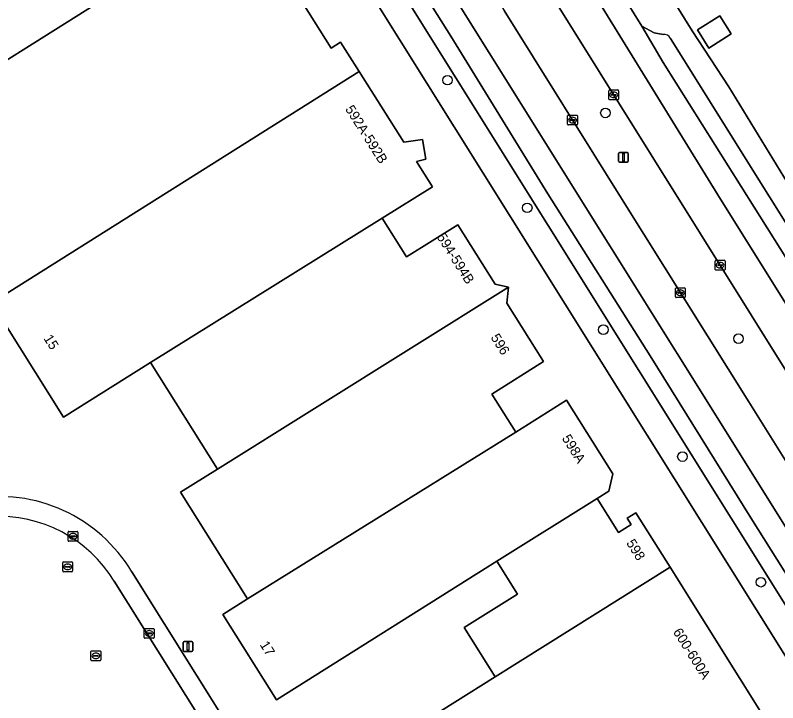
# Model space of a CAD drawing. Extents: x 158455 to 159797, y 387218 to 388672.
# Drawn here: x 158762.6 to 158840, y 387898.2 to 387968.1 of the extents above; entities that cross this region are included whole.
import ezdxf

# ---------------------------------------------------------------- set-up
doc = ezdxf.new("R2010")
doc.units = 0
for name, color, linetype in [('IMGEO_Berm_groen', 7, 'Continuous'), ('IMGEO_Boom', 7, 'Continuous'), ('IMGEO_Erf', 7, 'Continuous'), ('IMGEO_Kolk', 7, 'Continuous'), ('IMGEO_Lichtmast', 7, 'Continuous'), ('IMGEO_Pand', 7, 'Continuous'), ('IMGEO_Pand_nummerreeks', 7, 'Continuous'), ('IMGEO_Parkeervlak_open', 7, 'Continuous'), ('IMGEO_Rijbaan_lokaal_gesloten', 7, 'Continuous'), ('IMGEO_Rioolput', 7, 'Continuous'), ('IMGEO_Voetpad_open', 7, 'Continuous')]:
    doc.layers.add(name, color=color, linetype=linetype)

msp = doc.modelspace()

# ---------------------------------------------------------------- linework, layer by layer
at = {"layer": 'IMGEO_Berm_groen'}
msp.add_lwpolyline([(158816.975, 387970.262), (158811.283, 387979.426), (158807.11, 387976.831), (158812.237, 387968.597), (158824.322, 387949.219), (158837.096, 387928.793), (158852.17, 387904.676), (158856.298, 387907.238), (158851.263, 387915.352), (158842.383, 387929.569)], close=True, dxfattribs=at)
at = {"layer": 'IMGEO_Boom'}
for centre in [(158806.484, 387961.502), (158822.537, 387958.172), (158814.584, 387948.523), (158822.315, 387936.137), (158836.057, 387935.229), (158830.363, 387923.243), (158838.331, 387910.476)]:
    msp.add_circle(centre, 0.489, dxfattribs=at)
at = {"layer": 'IMGEO_Erf'}
for points in [[(158854.735, 387880.753), (158793.275, 387978.973), (158792.305, 387978.478), (158790.47, 387981.392), (158753.29, 388041.304)], [(158749.281, 387955.743), (158770.844, 387969.279), (158753.021, 387997.953)], [(158787.923, 387975.486), (158794.654, 387964.764), (158795.624, 387965.373), (158797.52, 387962.365), (158802.043, 387955.188), (158803.951, 387955.471), (158804.28, 387953.485), (158803.348, 387953.221), (158804.953, 387950.663), (158799.855, 387947.465), (158802.32, 387943.534), (158807.539, 387946.808), (158811.325, 387940.773), (158812.686, 387940.462), (158812.506, 387938.845), (158816.236, 387932.898), (158810.985, 387929.604), (158813.419, 387925.724), (158818.595, 387928.97), (158823.283, 387921.495), (158822.88, 387919.738), (158821.691, 387918.992), (158823.867, 387915.525), (158825.147, 387916.328), (158824.743, 387916.971), (158825.634, 387917.53), (158829.104, 387912), (158839.832, 387894.906)], [(158826.221, 387974.793), (158831.334, 387966.514), (158835.07, 387960.815), (158842.141, 387949.248), (158843.316, 387949.991), (158853.96, 387956.721), (158850.974, 387961.5), (158846.775, 387958.876), (158845.515, 387960.893), (158849.689, 387963.501), (158846.777, 387968.156)], [(158811.337, 387900.849), (158808.188, 387905.866), (158813.602, 387909.264), (158811.507, 387912.599), (158789.112, 387898.534), (158783.665, 387907.21), (158786.163, 387908.778), (158779.36, 387919.615), (158783.112, 387921.971), (158776.307, 387932.809), (158767.448, 387927.248), (158760.153, 387938.869)], [(158774.412, 387911.516), (158810.725, 387853.499), (158813.329, 387855.1), (158814.288, 387855.778), (158828.822, 387864.767), (158823.515, 387873.222), (158823.877, 387873.45), (158821.045, 387877.964), (158816.451, 387875.081), (158814.132, 387878.775), (158805.657, 387873.457), (158794.929, 387890.552), (158811.337, 387900.849)]]:
    msp.add_lwpolyline(points, dxfattribs=at)
msp.add_lwpolyline([(158831.874, 387966.612), (158834.159, 387968.04), (158835.311, 387966.196), (158833.027, 387964.768)], close=True, dxfattribs=at)
msp.add_arc((158760.897, 387903.456), 15.736, 30.80953, 100.02614, dxfattribs=at)
at = {"layer": 'IMGEO_Kolk'}
for p, q in [((158822.878, 387959.578), (158822.878, 387960.43)), ((158822.953, 387960.504), (158823.805, 387960.504)), ((158823.879, 387960.43), (158823.879, 387959.578)), ((158823.137, 387959.998), (158823.137, 387960.01)), ((158823.575, 387959.961), (158823.177, 387959.961)), ((158823.18, 387960.047), (158823.578, 387960.047)), ((158823.389, 387959.724), (158823.364, 387959.724)), ((158823.366, 387960.284), (158823.391, 387960.284)), ((158823.621, 387960.01), (158823.621, 387959.998)), ((158823.805, 387959.504), (158822.953, 387959.504)), ((158818.691, 387957.02), (158818.691, 387957.872)), ((158818.766, 387957.946), (158819.618, 387957.946)), ((158818.95, 387957.44), (158818.95, 387957.452)), ((158819.388, 387957.403), (158818.99, 387957.403)), ((158818.993, 387957.489), (158819.391, 387957.489)), ((158819.179, 387957.726), (158819.204, 387957.726)), ((158819.434, 387957.452), (158819.434, 387957.44)), ((158819.692, 387957.872), (158819.692, 387957.02)), ((158819.618, 387956.946), (158818.766, 387956.946)), ((158819.202, 387957.166), (158819.177, 387957.166)), ((158833.686, 387942.268), (158833.686, 387943.12)), ((158833.761, 387943.194), (158834.613, 387943.194)), ((158833.945, 387942.688), (158833.945, 387942.7)), ((158834.383, 387942.651), (158833.985, 387942.651)), ((158833.988, 387942.737), (158834.386, 387942.737)), ((158834.174, 387942.974), (158834.199, 387942.974)), ((158834.429, 387942.7), (158834.429, 387942.688)), ((158834.687, 387943.12), (158834.687, 387942.268)), ((158834.613, 387942.194), (158833.761, 387942.194)), ((158834.197, 387942.414), (158834.172, 387942.414)), ((158829.652, 387939.471), (158829.652, 387940.323)), ((158829.727, 387940.397), (158830.579, 387940.397)), ((158830.653, 387940.323), (158830.653, 387939.471)), ((158829.911, 387939.891), (158829.911, 387939.903)), ((158830.349, 387939.854), (158829.951, 387939.854)), ((158829.954, 387939.94), (158830.352, 387939.94)), ((158830.163, 387939.617), (158830.138, 387939.617)), ((158830.14, 387940.177), (158830.165, 387940.177)), ((158830.395, 387939.903), (158830.395, 387939.891)), ((158830.579, 387939.397), (158829.727, 387939.397)), ((158767.922, 387914.715), (158767.922, 387915.567)), ((158767.997, 387915.641), (158768.849, 387915.641)), ((158768.923, 387915.567), (158768.923, 387914.715)), ((158768.181, 387915.135), (158768.181, 387915.147)), ((158768.619, 387915.098), (158768.221, 387915.098)), ((158768.224, 387915.184), (158768.622, 387915.184)), ((158768.433, 387914.861), (158768.408, 387914.861)), ((158768.41, 387915.421), (158768.435, 387915.421)), ((158768.665, 387915.147), (158768.665, 387915.135)), ((158768.849, 387914.641), (158767.997, 387914.641)), ((158775.67, 387904.847), (158775.67, 387905.699)), ((158775.745, 387905.773), (158776.597, 387905.773)), ((158776.158, 387905.553), (158776.183, 387905.553)), ((158776.671, 387905.699), (158776.671, 387904.847)), ((158776.597, 387904.773), (158775.745, 387904.773)), ((158775.929, 387905.267), (158775.929, 387905.279)), ((158776.367, 387905.23), (158775.969, 387905.23)), ((158775.972, 387905.316), (158776.37, 387905.316)), ((158776.181, 387904.993), (158776.156, 387904.993)), ((158776.413, 387905.279), (158776.413, 387905.267))]:
    msp.add_line(p, q, dxfattribs=at)
for points in [[(158822.878, 387959.578), (158822.878, 387960.43)], [(158822.953, 387960.504), (158823.805, 387960.504)], [(158823.879, 387960.43), (158823.879, 387959.578)], [(158823.805, 387959.504), (158822.953, 387959.504)], [(158818.691, 387957.02), (158818.691, 387957.872)], [(158818.766, 387957.946), (158819.618, 387957.946)], [(158819.692, 387957.872), (158819.692, 387957.02)], [(158819.618, 387956.946), (158818.766, 387956.946)], [(158833.686, 387942.268), (158833.686, 387943.12)], [(158833.761, 387943.194), (158834.613, 387943.194)], [(158834.687, 387943.12), (158834.687, 387942.268)], [(158834.613, 387942.194), (158833.761, 387942.194)], [(158829.652, 387939.471), (158829.652, 387940.323)], [(158829.727, 387940.397), (158830.579, 387940.397)], [(158830.653, 387940.323), (158830.653, 387939.471)], [(158830.579, 387939.397), (158829.727, 387939.397)], [(158767.922, 387914.715), (158767.922, 387915.567)], [(158767.997, 387915.641), (158768.849, 387915.641)], [(158768.923, 387915.567), (158768.923, 387914.715)], [(158768.849, 387914.641), (158767.997, 387914.641)], [(158775.67, 387904.847), (158775.67, 387905.699)], [(158775.745, 387905.773), (158776.597, 387905.773)], [(158776.671, 387905.699), (158776.671, 387904.847)], [(158776.597, 387904.773), (158775.745, 387904.773)]]:
    msp.add_lwpolyline(points, dxfattribs=at)
for centre, radius, start, end in [((158822.955, 387960.428), 0.0765, 91.55205, 178.44795), ((158822.955, 387960.428), 0.0765, 91.55205, 178.44795), ((158823.803, 387960.428), 0.0765, 1.55205, 88.44795), ((158823.803, 387960.428), 0.0765, 1.55205, 88.44795), ((158823.177, 387960.007), 0.0403, 85.87752, 175.75265), ((158823.174, 387959.997), 0.0366, 178.93798, 274.71019), ((158823.578, 387960.004), 0.043, 264.86636, 352.45326), ((158823.582, 387960.009), 0.0386, 1.73085, 96.63898), ((158822.955, 387959.58), 0.0765, 181.55205, 268.44795), ((158822.955, 387959.58), 0.0765, 181.55205, 268.44795), ((158823.803, 387959.58), 0.0765, 271.55205, 358.44795), ((158823.803, 387959.58), 0.0765, 271.55205, 358.44795), ((158818.768, 387957.87), 0.0765, 91.55205, 178.44795), ((158818.768, 387957.87), 0.0765, 91.55205, 178.44795), ((158818.99, 387957.449), 0.0403, 85.87752, 175.75265), ((158818.987, 387957.439), 0.0366, 178.93798, 274.71019), ((158819.391, 387957.446), 0.043, 264.86636, 352.45326), ((158819.395, 387957.451), 0.0386, 1.73085, 96.63898), ((158819.616, 387957.87), 0.0765, 1.55205, 88.44795), ((158819.616, 387957.87), 0.0765, 1.55205, 88.44795), ((158818.768, 387957.022), 0.0765, 181.55205, 268.44795), ((158818.768, 387957.022), 0.0765, 181.55205, 268.44795), ((158819.616, 387957.022), 0.0765, 271.55205, 358.44795), ((158819.616, 387957.022), 0.0765, 271.55205, 358.44795), ((158833.763, 387943.118), 0.0765, 91.55205, 178.44795), ((158833.763, 387943.118), 0.0765, 91.55205, 178.44795), ((158833.985, 387942.697), 0.0403, 85.87752, 175.75265), ((158833.982, 387942.687), 0.0366, 178.93798, 274.71019), ((158834.386, 387942.694), 0.043, 264.86636, 352.45326), ((158834.39, 387942.699), 0.0386, 1.73085, 96.63898), ((158834.611, 387943.118), 0.0765, 1.55205, 88.44795), ((158834.611, 387943.118), 0.0765, 1.55205, 88.44795), ((158833.763, 387942.27), 0.0765, 181.55205, 268.44795), ((158833.763, 387942.27), 0.0765, 181.55205, 268.44795), ((158834.611, 387942.27), 0.0765, 271.55205, 358.44795), ((158834.611, 387942.27), 0.0765, 271.55205, 358.44795), ((158829.729, 387940.321), 0.0765, 91.55205, 178.44795), ((158829.729, 387940.321), 0.0765, 91.55205, 178.44795), ((158830.577, 387940.321), 0.0765, 1.55205, 88.44795), ((158830.577, 387940.321), 0.0765, 1.55205, 88.44795), ((158829.951, 387939.9), 0.0403, 85.87752, 175.75265), ((158829.948, 387939.89), 0.0366, 178.93798, 274.71019), ((158830.352, 387939.897), 0.043, 264.86636, 352.45326), ((158830.356, 387939.902), 0.0386, 1.73085, 96.63898), ((158829.729, 387939.473), 0.0765, 181.55205, 268.44795), ((158829.729, 387939.473), 0.0765, 181.55205, 268.44795), ((158830.577, 387939.473), 0.0765, 271.55205, 358.44795), ((158830.577, 387939.473), 0.0765, 271.55205, 358.44795), ((158767.999, 387915.565), 0.0765, 91.55205, 178.44795), ((158767.999, 387915.565), 0.0765, 91.55205, 178.44795), ((158768.847, 387915.565), 0.0765, 1.55205, 88.44795), ((158768.847, 387915.565), 0.0765, 1.55205, 88.44795), ((158767.999, 387914.717), 0.0765, 181.55205, 268.44795), ((158767.999, 387914.717), 0.0765, 181.55205, 268.44795), ((158768.221, 387915.144), 0.0403, 85.87752, 175.75265), ((158768.218, 387915.134), 0.0366, 178.93798, 274.71019), ((158768.622, 387915.141), 0.043, 264.86636, 352.45326), ((158768.626, 387915.146), 0.0386, 1.73085, 96.63898), ((158768.847, 387914.717), 0.0765, 271.55205, 358.44795), ((158768.847, 387914.717), 0.0765, 271.55205, 358.44795), ((158775.747, 387905.697), 0.0765, 91.55205, 178.44795), ((158775.747, 387905.697), 0.0765, 91.55205, 178.44795), ((158776.595, 387905.697), 0.0765, 1.55205, 88.44795), ((158776.595, 387905.697), 0.0765, 1.55205, 88.44795), ((158775.747, 387904.849), 0.0765, 181.55205, 268.44795), ((158775.747, 387904.849), 0.0765, 181.55205, 268.44795), ((158775.969, 387905.276), 0.0403, 85.87752, 175.75265), ((158775.966, 387905.266), 0.0366, 178.93798, 274.71019), ((158776.37, 387905.273), 0.043, 264.86636, 352.45326), ((158776.374, 387905.278), 0.0386, 1.73085, 96.63898), ((158776.595, 387904.849), 0.0765, 271.55205, 358.44795), ((158776.595, 387904.849), 0.0765, 271.55205, 358.44795)]:
    msp.add_arc(centre, radius, start, end, dxfattribs=at)
for centre, major_axis, ratio, start_param, end_param in [((158823.365, 387960.004), (-0.387, 0.002), 0.722429, 4.712389, 7.853982), ((158823.39, 387960.004), (-0.39, 0.002), 0.717154, 1.570796, 4.712389), ((158819.178, 387957.446), (-0.387, 0.002), 0.722429, 4.712389, 7.853982), ((158819.203, 387957.446), (-0.39, 0.002), 0.717154, 1.570796, 4.712389), ((158834.173, 387942.694), (-0.387, 0.002), 0.722429, 4.712389, 7.853982), ((158834.198, 387942.694), (-0.39, 0.002), 0.717154, 1.570796, 4.712389), ((158830.139, 387939.897), (-0.387, 0.002), 0.722429, 4.712389, 7.853982), ((158830.164, 387939.897), (-0.39, 0.002), 0.717154, 1.570796, 4.712389), ((158768.409, 387915.141), (-0.387, 0.002), 0.722429, 4.712389, 7.853982), ((158768.434, 387915.141), (-0.39, 0.002), 0.717154, 1.570796, 4.712389), ((158776.157, 387905.273), (-0.387, 0.002), 0.722429, 4.712389, 7.853982), ((158776.182, 387905.273), (-0.39, 0.002), 0.717154, 1.570796, 4.712389)]:
    msp.add_ellipse(centre, major_axis=major_axis, ratio=ratio, start_param=start_param, end_param=end_param, dxfattribs=at)
at = {"layer": 'IMGEO_Lichtmast'}
for p, q in [((158823.871, 387953.259), (158823.871, 387954.059)), ((158823.871, 387954.059), (158823.871, 387953.259)), ((158823.971, 387954.159), (158824.761, 387954.159)), ((158824.761, 387954.159), (158823.971, 387954.159)), ((158824.861, 387954.059), (158824.861, 387953.259)), ((158824.861, 387953.259), (158824.861, 387954.059)), ((158824.761, 387953.159), (158823.971, 387953.159)), ((158823.971, 387953.159), (158824.761, 387953.159)), ((158779.62, 387903.545), (158779.62, 387904.345)), ((158779.62, 387904.345), (158779.62, 387903.545)), ((158779.72, 387904.445), (158780.51, 387904.445)), ((158780.51, 387904.445), (158779.72, 387904.445)), ((158780.61, 387904.345), (158780.61, 387903.545)), ((158780.61, 387903.545), (158780.61, 387904.345)), ((158780.51, 387903.445), (158779.72, 387903.445)), ((158779.72, 387903.445), (158780.51, 387903.445))]:
    msp.add_line(p, q, dxfattribs=at)
for points in [[(158824.291, 387954.034), (158824.441, 387954.034), (158824.441, 387953.284), (158824.291, 387953.284), (158824.291, 387954.034)], [(158780.04, 387904.32), (158780.19, 387904.32), (158780.19, 387903.57), (158780.04, 387903.57), (158780.04, 387904.32)]]:
    msp.add_lwpolyline(points, dxfattribs=at)
for centre, start, end in [((158823.971, 387954.059), 90, 180), ((158823.971, 387954.059), 90, 180), ((158824.761, 387954.059), 0, 90), ((158824.761, 387954.059), 360, 90), ((158823.971, 387953.259), 180, 270), ((158823.971, 387953.259), 180, 270), ((158824.761, 387953.259), 270, 0), ((158824.761, 387953.259), 270, 0), ((158779.72, 387904.345), 90, 180), ((158779.72, 387904.345), 90, 180), ((158780.51, 387904.345), 0, 90), ((158780.51, 387904.345), 360, 90), ((158779.72, 387903.545), 180, 270), ((158779.72, 387903.545), 180, 270), ((158780.51, 387903.545), 270, 0), ((158780.51, 387903.545), 270, 0)]:
    msp.add_arc(centre, 0.1, start, end, dxfattribs=at)
at = {"layer": 'IMGEO_Pand'}
for points in [[(158758.286, 388025.218), (158746.563, 388017.931), (158757.32, 388000.625), (158756.314, 388000), (158753.021, 387997.953), (158770.844, 387969.279), (158749.281, 387955.743), (158745.046, 387953.084), (158755.718, 387936.084), (158760.153, 387938.869), (158797.52, 387962.365), (158795.624, 387965.373), (158794.654, 387964.764), (158787.923, 387975.486), (158788.935, 387976.121), (158786.995, 387979.213), (158773.954, 388000), (158765.132, 388014.2), (158763.942, 388013.46), (158762.622, 388015.583), (158763.813, 388016.323)], [(158831.874, 387966.612), (158833.027, 387964.768), (158835.311, 387966.196), (158834.159, 387968.04)], [(158776.307, 387932.809), (158799.855, 387947.465), (158804.953, 387950.663), (158803.348, 387953.221), (158804.28, 387953.485), (158803.951, 387955.471), (158802.043, 387955.188), (158797.52, 387962.365), (158760.153, 387938.869), (158767.448, 387927.248)], [(158812.686, 387940.462), (158811.325, 387940.773), (158807.539, 387946.808), (158802.32, 387943.534), (158799.855, 387947.465), (158776.307, 387932.809), (158783.112, 387921.971)], [(158813.419, 387925.724), (158810.985, 387929.604), (158816.236, 387932.898), (158812.506, 387938.845), (158812.686, 387940.462), (158783.112, 387921.971), (158779.36, 387919.615), (158786.163, 387908.778)], [(158821.691, 387918.992), (158822.88, 387919.738), (158823.283, 387921.495), (158818.595, 387928.97), (158813.419, 387925.724), (158786.163, 387908.778), (158783.665, 387907.21), (158789.112, 387898.534), (158811.507, 387912.599)], [(158829.104, 387912), (158825.634, 387917.53), (158824.743, 387916.971), (158825.147, 387916.328), (158823.867, 387915.525), (158821.691, 387918.992), (158811.507, 387912.599), (158813.602, 387909.264), (158808.188, 387905.866), (158811.337, 387900.849)], [(158811.337, 387900.849), (158794.929, 387890.552), (158805.657, 387873.457), (158814.132, 387878.775), (158839.832, 387894.906), (158829.104, 387912)]]:
    msp.add_lwpolyline(points, close=True, dxfattribs=at)
at = {"layer": 'IMGEO_Parkeervlak_open'}
for points in [[(158816.677, 387949.935), (158806.829, 387965.972), (158797.5, 387980.78), (158793.285, 387987.639), (158789.331, 387993.838), (158785.494, 388000), (158780.215, 388008.468)], [(158780.136, 388004.918), (158781.104, 388003.382), (158783.303, 388000), (158798.109, 387976.516), (158844.522, 387902.25), (158846.16, 387899.629), (158846.848, 387898.516), (158857.012, 387882.068)], [(158828.388, 387966.155), (158827.473, 387966.317), (158826.242, 387967.003), (158828.405, 387963.308), (158844.256, 387938.083), (158857.71, 387916.557), (158870.764, 387895.592), (158877.715, 387884.504), (158879.01, 387882.568)], [(158879.11, 387885.808), (158829.151, 387965.739)], [(158860.281, 387880.424), (158855.269, 387888.326), (158848.058, 387899.934), (158837.312, 387917.021), (158827.094, 387933.478), (158816.677, 387949.935)]]:
    msp.add_lwpolyline(points, dxfattribs=at)
msp.add_arc((158828.472, 387965.401), 0.759, 26.46985, 96.33028, dxfattribs=at)
at = {"layer": 'IMGEO_Rijbaan_lokaal_gesloten'}
msp.add_lwpolyline([(158857.71, 387916.557), (158844.256, 387938.083), (158828.405, 387963.308), (158826.242, 387967.003), (158821.291, 387974.98), (158819.155, 387978.39), (158808.574, 387995.299), (158807.699, 387996.716), (158779.748, 388041.252), (158777.679, 388039.896), (158792.31, 388017.418), (158834.227, 387949.391), (158871.964, 387889.05), (158887.922, 387863.502), (158890.244, 387864.932), (158881.497, 387878.849), (158879.01, 387882.568), (158877.715, 387884.504), (158870.764, 387895.592)], close=True, dxfattribs=at)
for points in [[(158871.964, 387889.05), (158834.227, 387949.391), (158792.31, 388017.418), (158777.679, 388039.896)], [(158774.752, 388037.976), (158786.347, 388019.403), (158787.973, 388016.798), (158798.463, 388000), (158806.797, 387986.65), (158811.283, 387979.426), (158816.975, 387970.262), (158842.383, 387929.569), (158851.263, 387915.352), (158856.298, 387907.238), (158856.412, 387907.055), (158857.076, 387905.984), (158857.412, 387905.443), (158858.993, 387902.895), (158866.508, 387890.905)], [(158853.754, 387895.444), (158836.678, 387922.775), (158822.801, 387944.946), (158810.737, 387964.275), (158802.455, 387977.515), (158793.995, 387991.082), (158785.095, 388005.301), (158780.694, 388012.384), (158779.563, 388013.342), (158778.332, 388014.385), (158774.869, 388017.05)], [(158780.215, 388008.468), (158785.494, 388000), (158789.331, 387993.838), (158793.285, 387987.639), (158797.5, 387980.78), (158806.829, 387965.972), (158816.677, 387949.935), (158827.094, 387933.478), (158837.312, 387917.021), (158848.058, 387899.934), (158855.269, 387888.326), (158860.281, 387880.424), (158864.153, 387874.318), (158873.777, 387859.01), (158875.717, 387855.924), (158877.701, 387857.148), (158853.754, 387895.444)], [(158802.455, 387977.515), (158810.737, 387964.275), (158822.801, 387944.946), (158836.678, 387922.775), (158853.754, 387895.444)], [(158861.396, 387889.771), (158853.284, 387902.882), (158852.923, 387903.465), (158852.297, 387904.473), (158852.17, 387904.676), (158837.096, 387928.793), (158824.322, 387949.219), (158812.237, 387968.597)], [(158776.253, 387891.744), (158777.049, 387890.477), (158782.923, 387894.163), (158772.625, 387910.573)]]:
    msp.add_lwpolyline(points, dxfattribs=at)
msp.add_arc((158760.885, 387903.424), 13.746, 31.34016, 93.18998, dxfattribs=at)
at = {"layer": 'IMGEO_Rioolput'}
for p, q in [((158767.385, 387911.619), (158767.385, 387912.471)), ((158767.46, 387912.545), (158768.312, 387912.545)), ((158768.386, 387912.471), (158768.386, 387911.619)), ((158767.644, 387912.039), (158767.644, 387912.051)), ((158768.082, 387912.002), (158767.684, 387912.002)), ((158767.687, 387912.088), (158768.085, 387912.088)), ((158767.896, 387911.765), (158767.871, 387911.765)), ((158767.873, 387912.325), (158767.898, 387912.325)), ((158768.128, 387912.051), (158768.128, 387912.039)), ((158768.312, 387911.545), (158767.46, 387911.545)), ((158770.25, 387902.573), (158770.25, 387903.425)), ((158770.325, 387903.499), (158771.177, 387903.499)), ((158770.738, 387903.279), (158770.763, 387903.279)), ((158771.251, 387903.425), (158771.251, 387902.573)), ((158771.177, 387902.499), (158770.325, 387902.499)), ((158770.509, 387902.993), (158770.509, 387903.005)), ((158770.947, 387902.956), (158770.549, 387902.956)), ((158770.552, 387903.042), (158770.95, 387903.042)), ((158770.761, 387902.719), (158770.736, 387902.719)), ((158770.993, 387903.005), (158770.993, 387902.993))]:
    msp.add_line(p, q, dxfattribs=at)
for points in [[(158767.385, 387911.619), (158767.385, 387912.471)], [(158767.46, 387912.545), (158768.312, 387912.545)], [(158768.386, 387912.471), (158768.386, 387911.619)], [(158768.312, 387911.545), (158767.46, 387911.545)], [(158770.25, 387902.573), (158770.25, 387903.425)], [(158770.325, 387903.499), (158771.177, 387903.499)], [(158771.251, 387903.425), (158771.251, 387902.573)], [(158771.177, 387902.499), (158770.325, 387902.499)]]:
    msp.add_lwpolyline(points, dxfattribs=at)
for centre, radius, start, end in [((158767.462, 387912.469), 0.0765, 91.55205, 178.44795), ((158767.462, 387912.469), 0.0765, 91.55205, 178.44795), ((158768.31, 387912.469), 0.0765, 1.55205, 88.44795), ((158768.31, 387912.469), 0.0765, 1.55205, 88.44795), ((158767.462, 387911.621), 0.0765, 181.55205, 268.44795), ((158767.462, 387911.621), 0.0765, 181.55205, 268.44795), ((158767.684, 387912.048), 0.0403, 85.87752, 175.75265), ((158767.681, 387912.038), 0.0366, 178.93798, 274.71019), ((158768.085, 387912.045), 0.043, 264.86636, 352.45326), ((158768.089, 387912.05), 0.0386, 1.73085, 96.63898), ((158768.31, 387911.621), 0.0765, 271.55205, 358.44795), ((158768.31, 387911.621), 0.0765, 271.55205, 358.44795), ((158770.327, 387903.423), 0.0765, 91.55205, 178.44795), ((158770.327, 387903.423), 0.0765, 91.55205, 178.44795), ((158771.175, 387903.423), 0.0765, 1.55205, 88.44795), ((158771.175, 387903.423), 0.0765, 1.55205, 88.44795), ((158770.327, 387902.575), 0.0765, 181.55205, 268.44795), ((158770.327, 387902.575), 0.0765, 181.55205, 268.44795), ((158770.549, 387903.002), 0.0403, 85.87752, 175.75265), ((158770.546, 387902.992), 0.0366, 178.93798, 274.71019), ((158770.95, 387902.999), 0.043, 264.86636, 352.45326), ((158770.954, 387903.004), 0.0386, 1.73085, 96.63898), ((158771.175, 387902.575), 0.0765, 271.55205, 358.44795), ((158771.175, 387902.575), 0.0765, 271.55205, 358.44795)]:
    msp.add_arc(centre, radius, start, end, dxfattribs=at)
for centre, major_axis, ratio, start_param, end_param in [((158767.872, 387912.045), (-0.387, 0.002), 0.722429, 4.712389, 7.853982), ((158767.897, 387912.045), (-0.39, 0.002), 0.717154, 1.570796, 4.712389), ((158770.737, 387902.999), (-0.387, 0.002), 0.722429, 4.712389, 7.853982), ((158770.762, 387902.999), (-0.39, 0.002), 0.717154, 1.570796, 4.712389)]:
    msp.add_ellipse(centre, major_axis=major_axis, ratio=ratio, start_param=start_param, end_param=end_param, dxfattribs=at)
at = {"layer": 'IMGEO_Voetpad_open'}
for points in [[(158831.334, 387966.514), (158826.221, 387974.793), (158827.359, 387975.532), (158825.428, 387978.622), (158823.292, 387982.041), (158820.433, 387986.616), (158818.2, 387990.263), (158816.22, 387993.495), (158814.961, 387995.567), (158813.957, 387997.174), (158812.156, 388000), (158804.148, 388012.735), (158801.869, 388013.247), (158798.408, 388018.757), (158797.295, 388020.528), (158796.197, 388019.813), (158793.639, 388023.916), (158778.006, 388048.991), (158777.07, 388050.354), (158773.887, 388055.513), (158773.46, 388055.233)], [(158772.646, 388052.678), (158776.275, 388046.877), (158779.748, 388041.252), (158807.699, 387996.716), (158808.574, 387995.299), (158819.155, 387978.39), (158821.291, 387974.98), (158826.242, 387967.003), (158827.473, 387966.317), (158828.388, 387966.155)], [(158750.225, 388044.567), (158751.855, 388042.396), (158752.718, 388041.901), (158753.29, 388041.304), (158790.47, 387981.392), (158792.305, 387978.478), (158793.275, 387978.973), (158854.735, 387880.753), (158857.012, 387882.068), (158846.848, 387898.516)], [(158846.848, 387898.516), (158846.424, 387898.252), (158844.098, 387901.986), (158844.522, 387902.25), (158798.109, 387976.516), (158783.303, 388000), (158781.104, 388003.382), (158780.136, 388004.918)], [(158876.692, 387896.643), (158874.508, 387900.137), (158871.689, 387904.628), (158869.443, 387908.222), (158866.856, 387912.361), (158866.053, 387913.683), (158864.703, 387912.884), (158857.682, 387924.302), (158858.892, 387925.071), (158857.988, 387926.56), (158855.389, 387930.719), (158853.175, 387934.262), (158850.342, 387938.765), (158848.346, 387941.959), (158846.058, 387945.62), (158844.659, 387947.867), (158843.316, 387949.991), (158842.141, 387949.248), (158835.07, 387960.815), (158831.334, 387966.514)], [(158829.151, 387965.739), (158879.11, 387885.808)], [(158772.625, 387910.573), (158782.923, 387894.163), (158809.048, 387852.533), (158810.725, 387853.499), (158774.412, 387911.516)]]:
    msp.add_lwpolyline(points, dxfattribs=at)
for centre, radius, start, end in [((158828.472, 387965.401), 0.759, 26.46985, 96.33028), ((158760.897, 387903.456), 15.736, 30.80953, 100.02614), ((158760.885, 387903.424), 13.746, 31.34016, 93.18998)]:
    msp.add_arc(centre, radius, start, end, dxfattribs=at)

# ---------------------------------------------------------------- texts
at = {"layer": 'IMGEO_Pand_nummerreeks'}
for s, rotation, p in [('592A-592B', 302.25471, (158796.051, 387958.564)), ('594-594B', 302.10261, (158805.358, 387945.579)), ('596', 302.12951, (158810.835, 387935.348)), ('15', 302.74724, (158765.398, 387935.254)), ('598A', 301.89635, (158818.075, 387925.106)), ('598', 301.90781, (158824.612, 387914.465)), ('600-600A', 302.11191, (158829.36, 387905.421)), ('17', 301.925, (158787.378, 387904.122))]:
    msp.add_text(s, height=1, rotation=rotation, dxfattribs=at).set_placement(p)

doc.saveas('drawing.dxf')
